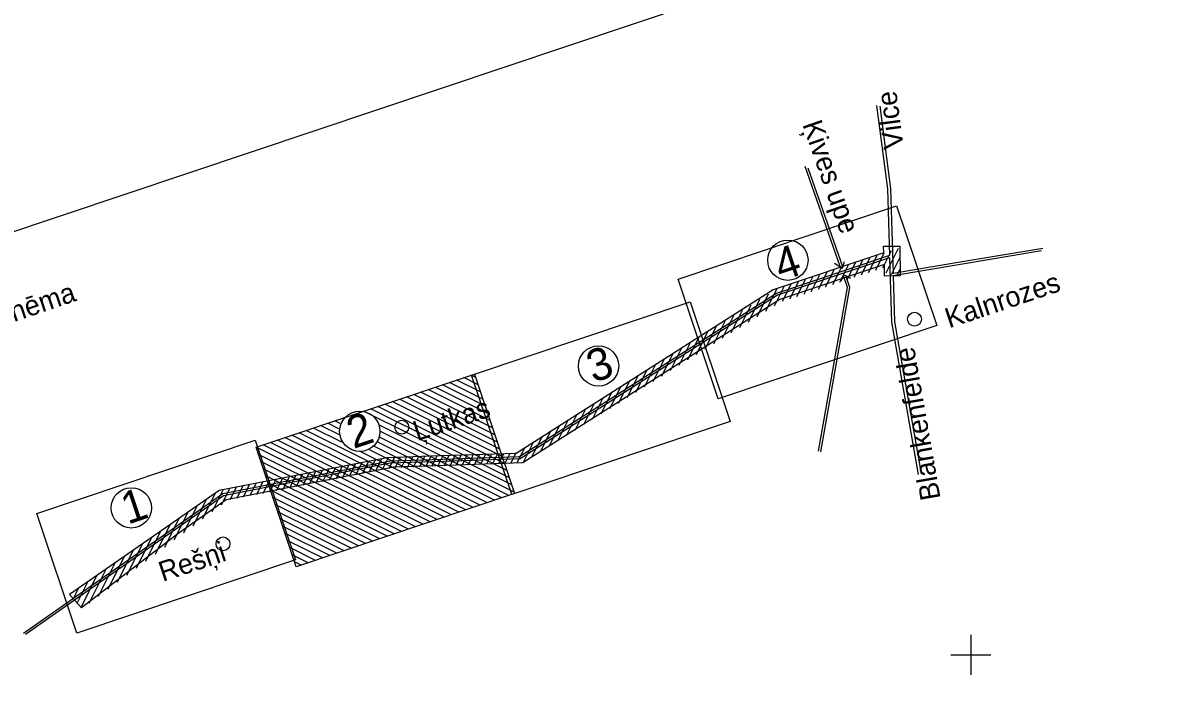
# Model space of a CAD drawing. Extents: x 469981 to 472086, y 246785 to 247785.
# Drawn here: x 470529 to 470614.3, y 247197.8 to 247247.3 of the extents above; entities that cross this region are included whole.
import ezdxf

# ---------------------------------------------------------------- set-up
doc = ezdxf.new("R2010")
doc.units = 0
for name, color, linetype in [('GEOD_ELEM_####_####_#', 7, 'Continuous'), ('RAMI_PLAN_####_TKST_#', 7, 'Continuous'), ('RELJ_NOGA_####_####_#', 7, 'Continuous'), ('RELJ_NOGL_####_####_#', 7, 'Continuous')]:
    doc.layers.add(name, color=color, linetype=linetype)

msp = doc.modelspace()

# ---------------------------------------------------------------- linework, layer by layer
at = {"layer": 'GEOD_ELEM_####_####_#'}
for p, q in [((470600, 247201.5), (470600, 247200)), ((470598.5, 247200), (470600, 247200)), ((470600, 247200), (470600, 247198.5)), ((470600, 247200), (470601.5, 247200))]:
    msp.add_line(p, q, dxfattribs=at)
at = {"layer": 'RAMI_PLAN_####_TKST_#'}
for p, q in [((470593.415, 247228.987), (470594.054, 247230.272)), ((470593.467, 247230.597), (470594.675, 247230.607)), ((470593.472, 247230.099), (470593.467, 247230.597)), ((470593.667, 247228.596), (470594.591, 247230.451)), ((470594.675, 247230.607), (470594.694, 247228.374)), ((470589.781, 247229.321), (470590.395, 247228.951)), ((470590.395, 247228.951), (470590.549, 247229.446)), ((470590.733, 247228.088), (470591.372, 247229.373)), ((470591.269, 247228.268), (470591.909, 247229.552)), ((470591.806, 247228.448), (470592.445, 247229.732)), ((470592.342, 247228.628), (470592.981, 247229.912)), ((470592.878, 247228.808), (470593.518, 247230.092)), ((470594.052, 247228.473), (470594.7, 247229.774)), ((470588.051, 247227.189), (470588.691, 247228.474)), ((470588.588, 247227.369), (470589.227, 247228.653)), ((470589.124, 247227.549), (470589.763, 247228.833)), ((470589.66, 247227.729), (470590.3, 247229.013)), ((470590.197, 247227.909), (470590.836, 247229.193)), ((470590.261, 247227.973), (470590.514, 247228.454)), ((470590.514, 247228.454), (470590.995, 247228.201)), ((470593.534, 247228.364), (470593.526, 247229.24)), ((470594.466, 247228.406), (470594.702, 247228.88)), ((470585.288, 247226.126), (470586.009, 247227.575)), ((470585.906, 247226.47), (470586.545, 247227.755)), ((470586.442, 247226.65), (470587.082, 247227.934)), ((470586.978, 247226.83), (470587.618, 247228.114)), ((470587.515, 247227.01), (470588.154, 247228.294)), ((470594.694, 247228.374), (470593.534, 247228.364)), ((470583.992, 247225.318), (470584.848, 247227.038)), ((470584.64, 247225.722), (470585.473, 247227.395)), ((470582.696, 247224.51), (470583.546, 247226.218)), ((470583.344, 247224.914), (470584.197, 247226.628)), ((470581.4, 247223.702), (470582.244, 247225.398)), ((470582.048, 247224.106), (470582.895, 247225.808)), ((470579.456, 247222.49), (470580.291, 247224.169)), ((470580.104, 247222.894), (470580.942, 247224.578)), ((470580.752, 247223.298), (470581.593, 247224.988)), ((470578.16, 247221.683), (470578.99, 247223.349)), ((470578.808, 247222.086), (470579.64, 247223.759)), ((470576.864, 247220.875), (470577.688, 247222.529)), ((470577.512, 247221.279), (470578.339, 247222.939)), ((470575.568, 247220.067), (470576.386, 247221.709)), ((470576.216, 247220.471), (470577.037, 247222.119)), ((470563.115, 247220.228), (470562.047, 247220.759)), ((470562.935, 247220.764), (470562.584, 247220.939)), ((470574.272, 247219.259), (470575.084, 247220.89)), ((470574.92, 247219.663), (470575.735, 247221.299)), ((470563.834, 247218.082), (470559.902, 247220.04)), ((470563.654, 247218.619), (470560.438, 247220.22)), ((470563.474, 247219.155), (470560.974, 247220.4)), ((470563.294, 247219.691), (470561.511, 247220.579)), ((470572.976, 247218.451), (470573.782, 247220.07)), ((470573.624, 247218.855), (470574.433, 247220.48)), ((470564.733, 247215.401), (470557.22, 247219.141)), ((470564.553, 247215.937), (470557.756, 247219.321)), ((470564.373, 247216.473), (470558.293, 247219.501)), ((470564.193, 247217.01), (470558.829, 247219.68)), ((470564.013, 247217.546), (470559.365, 247219.86)), ((470571.68, 247217.643), (470572.48, 247219.25)), ((470572.328, 247218.047), (470573.131, 247219.66)), ((470565.632, 247212.719), (470554.538, 247218.242)), ((470565.452, 247213.255), (470555.075, 247218.422)), ((470565.272, 247213.792), (470555.611, 247218.602)), ((470565.092, 247214.328), (470556.147, 247218.782)), ((470564.912, 247214.864), (470556.684, 247218.961)), ((470570.384, 247216.835), (470571.179, 247218.43)), ((470571.032, 247217.239), (470571.829, 247218.84)), ((470552.677, 247216.934), (470551.856, 247217.343)), ((470552.782, 247217.329), (470552.393, 247217.523)), ((470553, 247217.668), (470552.929, 247217.703)), ((470553.506, 247217.862), (470553.465, 247217.883)), ((470554.057, 247218.035), (470554.002, 247218.062)), ((470569.088, 247216.027), (470569.877, 247217.611)), ((470569.736, 247216.431), (470570.528, 247218.02)), ((470561.662, 247210.674), (470549.711, 247216.624)), ((470562.198, 247210.854), (470550.247, 247216.804)), ((470552.898, 247215.931), (470550.784, 247216.984)), ((470552.726, 247216.464), (470551.32, 247217.163)), ((470565.811, 247212.182), (470555.731, 247217.201)), ((470565.416, 247211.932), (470555.813, 247216.714)), ((470567.792, 247215.219), (470568.575, 247216.791)), ((470568.44, 247215.623), (470569.226, 247217.201)), ((470558.98, 247209.775), (470547.029, 247215.725)), ((470559.516, 247209.955), (470547.566, 247215.905)), ((470560.053, 247210.134), (470548.102, 247216.085)), ((470560.589, 247210.314), (470548.638, 247216.265)), ((470561.125, 247210.494), (470549.175, 247216.444)), ((470564.344, 247211.573), (470555.604, 247215.924)), ((470564.88, 247211.753), (470555.731, 247216.308)), ((470566.501, 247214.421), (470567.273, 247215.971)), ((470567.144, 247214.815), (470567.924, 247216.381)), ((470558.444, 247209.595), (470546.493, 247215.545)), ((470557.907, 247209.415), (470546.673, 247215.009)), ((470562.734, 247211.033), (470554.244, 247215.261)), ((470563.271, 247211.213), (470554.982, 247215.34)), ((470563.807, 247211.393), (470555.313, 247215.622)), ((470556.444, 247213.965), (470556.853, 247214.787)), ((470556.909, 247214.001), (470557.308, 247214.804)), ((470557.365, 247214.021), (470557.764, 247214.821)), ((470557.822, 247214.041), (470558.219, 247214.838)), ((470558.279, 247214.061), (470558.674, 247214.855)), ((470558.736, 247214.081), (470559.13, 247214.872)), ((470559.193, 247214.101), (470559.585, 247214.889)), ((470559.649, 247214.121), (470560.04, 247214.906)), ((470560.106, 247214.141), (470560.496, 247214.923)), ((470560.563, 247214.161), (470560.951, 247214.94)), ((470561.02, 247214.181), (470561.406, 247214.958)), ((470561.477, 247214.201), (470561.862, 247214.975)), ((470561.933, 247214.221), (470562.317, 247214.992)), ((470562.39, 247214.241), (470562.772, 247215.009)), ((470562.847, 247214.261), (470563.228, 247215.026)), ((470563.304, 247214.281), (470563.683, 247215.043)), ((470563.761, 247214.301), (470564.138, 247215.06)), ((470564.217, 247214.321), (470564.594, 247215.077)), ((470564.674, 247214.341), (470565.049, 247215.094)), ((470565.131, 247214.361), (470565.504, 247215.111)), ((470565.588, 247214.381), (470565.971, 247215.151)), ((470566.045, 247214.401), (470566.622, 247215.561)), ((470557.371, 247209.236), (470546.852, 247214.473)), ((470556.835, 247209.056), (470547.032, 247213.936)), ((470551.986, 247213.089), (470552.447, 247214.015)), ((470552.481, 247213.186), (470552.943, 247214.113)), ((470552.977, 247213.284), (470553.438, 247214.21)), ((470553.472, 247213.381), (470553.933, 247214.307)), ((470553.967, 247213.479), (470554.428, 247214.405)), ((470554.463, 247213.576), (470554.924, 247214.502)), ((470554.958, 247213.673), (470555.419, 247214.599)), ((470555.453, 247213.771), (470555.914, 247214.697)), ((470555.949, 247213.868), (470556.398, 247214.77)), ((470556.298, 247208.876), (470547.212, 247213.4)), ((470547.528, 247212.213), (470547.99, 247213.14)), ((470548.024, 247212.31), (470548.485, 247213.237)), ((470548.519, 247212.408), (470548.98, 247213.334)), ((470549.014, 247212.505), (470549.476, 247213.432)), ((470549.509, 247212.602), (470549.971, 247213.529)), ((470550.005, 247212.7), (470550.466, 247213.626)), ((470550.5, 247212.797), (470550.961, 247213.724)), ((470550.995, 247212.894), (470551.457, 247213.821)), ((470551.491, 247212.992), (470551.952, 247213.918)), ((470543.2, 247210.699), (470544.027, 247212.361)), ((470543.908, 247211.224), (470544.523, 247212.459)), ((470544.556, 247211.629), (470545.018, 247212.556)), ((470545.052, 247211.726), (470545.513, 247212.653)), ((470545.547, 247211.823), (470546.009, 247212.75)), ((470546.042, 247211.921), (470546.504, 247212.848)), ((470546.538, 247212.018), (470546.999, 247212.945)), ((470547.033, 247212.115), (470547.494, 247213.042)), ((470555.762, 247208.696), (470547.392, 247212.864)), ((470555.226, 247208.516), (470547.572, 247212.327)), ((470541.784, 247209.65), (470542.794, 247211.679)), ((470542.492, 247210.175), (470543.479, 247212.156)), ((470554.689, 247208.337), (470547.751, 247211.791)), ((470540.368, 247208.601), (470541.425, 247210.724)), ((470541.076, 247209.125), (470542.109, 247211.201)), ((470554.153, 247208.157), (470547.931, 247211.255)), ((470553.616, 247207.977), (470548.111, 247210.718)), ((470538.952, 247207.552), (470540.055, 247209.768)), ((470539.66, 247208.076), (470540.74, 247210.246)), ((470553.08, 247207.797), (470548.291, 247210.182)), ((470537.536, 247206.503), (470538.686, 247208.813)), ((470538.244, 247207.027), (470539.371, 247209.291)), ((470552.544, 247207.617), (470548.471, 247209.645)), ((470552.007, 247207.438), (470548.65, 247209.109)), ((470536.828, 247205.978), (470538.002, 247208.336)), ((470551.471, 247207.258), (470548.83, 247208.573)), ((470550.935, 247207.078), (470549.01, 247208.036)), ((470535.412, 247204.929), (470536.632, 247207.381)), ((470536.12, 247205.454), (470537.317, 247207.858)), ((470550.398, 247206.898), (470549.19, 247207.5)), ((470533.996, 247203.88), (470535.263, 247206.425)), ((470534.704, 247204.405), (470535.948, 247206.903)), ((470549.862, 247206.718), (470549.369, 247206.964)), ((470533.101, 247203.878), (470533.894, 247205.47)), ((470533.389, 247203.559), (470534.578, 247205.948)), ((470532.813, 247204.196), (470533.209, 247204.993)), ((470532.525, 247204.515), (470533.421, 247203.522))]:
    msp.add_line(p, q, dxfattribs=at)
for points in [[(471098.888, 247111.821), (470587.835, 246940.515), (470494.078, 247220.22), (471005.131, 247391.526)], [(470597.439, 247224.662), (470581.085, 247219.18), (470578.085, 247228.13), (470594.439, 247233.612)], [(470581.977, 247217.484), (470565.624, 247212.002), (470562.623, 247220.952), (470578.977, 247226.434)], [(470565.847, 247212.077), (470549.493, 247206.595), (470546.493, 247215.545), (470562.847, 247221.027)], [(470549.433, 247207.116), (470533.079, 247201.634), (470530.079, 247210.585), (470546.433, 247216.067)]]:
    msp.add_lwpolyline(points, close=True, dxfattribs=at)
for points in [[(470592.938, 247241.144), (470593.761, 247234.882), (470593.908, 247229.897)], [(470593.169, 247241.094), (470593.983, 247234.9), (470594.17, 247228.551)], [(470590.206, 247229.086), (470587.589, 247236.566)], [(470590.411, 247229.042), (470587.823, 247236.442)], [(470605.378, 247230.427), (470599.042, 247229.367), (470594.17, 247228.551)], [(470605.278, 247230.247), (470599.068, 247229.207), (470594.175, 247228.388)], [(470593.908, 247229.897), (470585.446, 247227.061), (470566.204, 247214.821), (470560.482, 247214.63), (470556.522, 247214.498), (470543.991, 247212.048), (470540.374, 247209.515), (470529.069, 247201.598)], [(470593.912, 247229.738), (470585.512, 247226.922), (470566.25, 247214.67), (470560.487, 247214.478), (470556.539, 247214.346), (470544.052, 247211.905), (470540.462, 247209.39), (470529.239, 247201.531)], [(470593.472, 247230.099), (470585.194, 247227.324), (470565.952, 247215.084), (470560.23, 247214.893), (470556.27, 247214.761), (470543.739, 247212.311), (470540.122, 247209.778), (470532.525, 247204.515)], [(470593.912, 247229.738), (470594.054, 247224.92), (470596.054, 247213.513)], [(470593.526, 247229.24), (470585.701, 247226.617), (470566.459, 247214.377), (470560.738, 247214.186), (470556.777, 247214.054), (470544.247, 247211.604), (470540.63, 247209.071), (470533.421, 247203.522)], [(470588.601, 247215.24), (470590.76, 247227.5), (470590.454, 247228.377)], [(470588.777, 247215.209), (470590.945, 247227.515), (470590.635, 247228.401)], [(470594.175, 247228.388), (470594.276, 247224.942), (470596.274, 247213.55)]]:
    msp.add_lwpolyline(points, dxfattribs=at)
for centre, radius in [((470586.297, 247229.548), 1.509), ((470595.777, 247225.13), 0.518), ((470572.128, 247221.632), 1.509), ((470554.256, 247216.741), 1.509), ((470557.395, 247217.051), 0.518), ((470537.151, 247211.007), 1.509), ((470544.017, 247208.309), 0.518)]:
    msp.add_circle(centre, radius, dxfattribs=at)
at = {"layer": 'RELJ_NOGA_####_####_#'}
for points in [[(470606.183, 247176.676), (470630.141, 247182.622), (470654.6, 247188.654), (470677.992, 247194.648), (470707.339, 247201.373), (470732.104, 247207.628), (470762.069, 247214.507), (470787.98, 247219.522), (470817.319, 247223.525), (470842.975, 247225.157), (470861.302, 247225.322)], [(470443.762, 247118.331), (470443.88, 247120.814), (470444.471, 247122.233), (470445.96, 247123.747), (470447.74, 247124.344), (470466.701, 247130.323), (470490.205, 247137.037), (470509.522, 247142.633), (470536.42, 247149.583), (470558.637, 247154.955), (470585.403, 247162.504), (470607.875, 247168.231), (470633.412, 247175.414), (470656.062, 247180.759), (470680.788, 247187.471), (470708.074, 247193.923), (470734.191, 247200.317), (470761.697, 247206.456), (470789.773, 247212.754), (470817.257, 247216.179), (470830.019, 247217.144), (470848.586, 247217.569), (470861.752, 247217.476), (470881.066, 247214.264), (470905.336, 247205.96), (470932.738, 247196.11), (470958.906, 247187.141), (470978.102, 247181.086)]]:
    msp.add_spline(points, degree=3, dxfattribs=at)
at = {"layer": 'RELJ_NOGL_####_####_#'}
for points in [[(470606.139, 247178.172), (470629.32, 247183.824), (470654.592, 247190.289), (470677.819, 247195.89), (470706.841, 247202.594), (470731.579, 247208.797), (470762.066, 247216.088), (470787.493, 247220.75), (470816.99, 247225.543), (470831.338, 247226.448), (470860.897, 247226.774)], [(470444.636, 247118.184), (470444.802, 247120.028), (470444.991, 247120.926), (470445.558, 247121.73), (470446.408, 247122.251), (470448.872, 247122.621), (470466.486, 247128.526), (470490.665, 247135.792), (470509.603, 247140.94), (470537.55, 247147.945), (470558.966, 247153.542), (470586.086, 247160.934), (470607.922, 247166.842), (470634.241, 247173.648), (470681.28, 247185.658), (470708.292, 247192.117), (470734.878, 247198.699), (470761.457, 247204.922), (470790.498, 247211.068), (470817.148, 247213.701), (470830.618, 247215.209), (470848.022, 247215.369), (470862.099, 247215.472), (470880.883, 247212.412), (470904.425, 247203.826), (470932.21, 247193.701), (470958.298, 247186.024), (470977.689, 247180.167)]]:
    msp.add_spline(points, degree=3, dxfattribs=at)

# ---------------------------------------------------------------- texts
at = {"layer": 'RAMI_PLAN_####_TKST_#'}
for s, height, rotation, p in [('Vilce', 1.5, 97.4902, (470594.972, 247237.982)), ('Ķives upe', 1.5, 289.27959, (470587.367, 247239.719)), ('4', 2.4, 18.53122, (470585.77, 247227.957)), ('Kalnrozes', 1.5, 18.53122, (470598.367, 247224.443)), ('Objekta izvietojuma shēma', 1.5, 18.75271, (470510.314, 247218.788)), ('3', 2.4, 18.53122, (470571.731, 247220.356)), ('Blankenfelde', 1.5, 99.9444, (470597.734, 247211.714)), ('Ļutkas', 1.5, 18.53122, (470558.546, 247215.996)), ('2', 2.4, 18.53122, (470553.777, 247215.411)), ('1', 2.4, 18.53122, (470536.883, 247209.748)), ('Rešņi', 1.5, 18.53122, (470539.505, 247205.458))]:
    msp.add_text(s, height=height, rotation=rotation, dxfattribs=at).set_placement(p)

doc.saveas('drawing.dxf')
